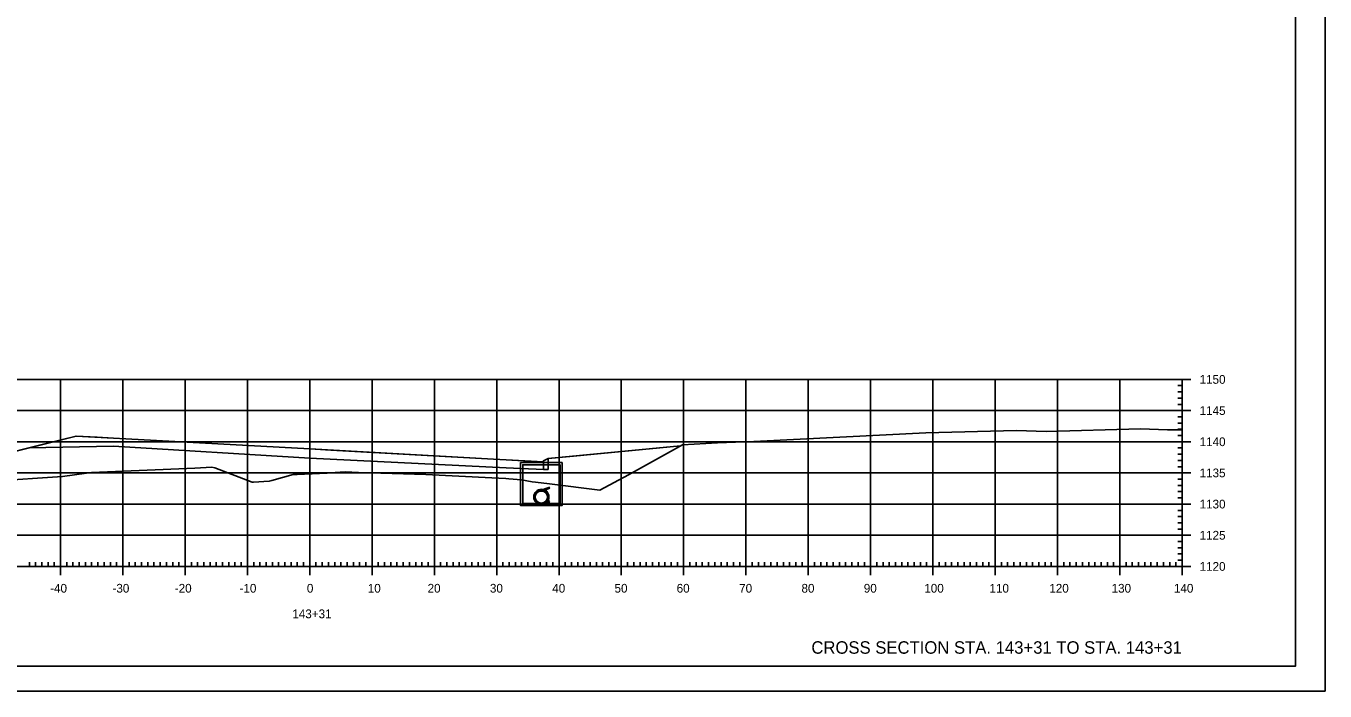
# Model space of a CAD drawing. Extents: x 1322838 to 1324533, y 339903 to 351025.
# Drawn here: x 1324118.6 to 1324327.1, y 343023.7 to 343130.4 of the extents above; entities that cross this region are included whole.
import ezdxf

# ---------------------------------------------------------------- set-up
doc = ezdxf.new("R2010")
doc.units = 0
for name, color, linetype in [('R_Alt Surface', 7, 'Continuous'), ('R_Axis', 7, 'Continuous'), ('R_Axis Annot', 7, 'Continuous'), ('R_Border', 7, 'Continuous'), ('R_Draft', 7, 'Continuous'), ('R_Exist Surface', 7, 'Continuous'), ('R_Fin Surface', 7, 'Continuous'), ('R_Grid', 7, 'Continuous'), ('R_No Plot', 7, 'Continuous')]:
    doc.layers.add(name, color=color, linetype=linetype)

msp = doc.modelspace()

# ---------------------------------------------------------------- linework, layer by layer
for points in [[(1324126.64, 343064.61), (1324104.64, 343059.11), (1324089.24, 343053.98)], [(1324201.64, 343060.49), (1324201.65, 343060.65), (1324202.4, 343060.99), (1324223.62, 343063.03), (1324223.62, 343063.03)]]:
    msp.add_lwpolyline(points)
at = {"layer": 'R_Alt Surface'}
for points in [[(1324119.06, 343062.72), (1324132.64, 343062.99), (1324164.14, 343061.05), (1324195.64, 343059.52), (1324201.64, 343059.23)], [(1324201.64, 343060.49), (1324201.64, 343059.23)], [(1324201.64, 343059.23), (1324202.4, 343059.23)], [(1324202.4, 343059.23), (1324202.4, 343060.99)]]:
    msp.add_lwpolyline(points, dxfattribs=at)
at = {"layer": 'R_Axis'}
for p, q in [((1324305.54, 343073.7), (1324302.74, 343073.7)), ((1324304.14, 343043.7), (1324304.14, 343073.7)), ((1324304.14, 343072.7), (1324303.44, 343072.7)), ((1324304.14, 343071.7), (1324303.44, 343071.7)), ((1324304.14, 343070.7), (1324303.44, 343070.7)), ((1324304.14, 343069.7), (1324303.44, 343069.7)), ((1324305.54, 343068.7), (1324302.74, 343068.7)), ((1324304.14, 343067.7), (1324303.44, 343067.7)), ((1324304.14, 343066.7), (1324303.44, 343066.7)), ((1324304.14, 343065.7), (1324303.44, 343065.7)), ((1324305.54, 343063.7), (1324302.74, 343063.7)), ((1324304.14, 343064.7), (1324303.44, 343064.7)), ((1324304.14, 343062.7), (1324303.44, 343062.7)), ((1324304.14, 343061.7), (1324303.44, 343061.7)), ((1324304.14, 343060.7), (1324303.44, 343060.7)), ((1324304.14, 343059.7), (1324303.44, 343059.7)), ((1324305.54, 343058.7), (1324302.74, 343058.7)), ((1324304.14, 343057.7), (1324303.44, 343057.7)), ((1324304.14, 343056.7), (1324303.44, 343056.7)), ((1324304.14, 343055.7), (1324303.44, 343055.7)), ((1324305.54, 343053.7), (1324302.74, 343053.7)), ((1324304.14, 343054.7), (1324303.44, 343054.7)), ((1324304.14, 343052.7), (1324303.44, 343052.7)), ((1324304.14, 343051.7), (1324303.44, 343051.7)), ((1324305.54, 343048.7), (1324302.74, 343048.7)), ((1324304.14, 343050.7), (1324303.44, 343050.7)), ((1324304.14, 343049.7), (1324303.44, 343049.7)), ((1324304.14, 343047.7), (1324303.44, 343047.7)), ((1324304.14, 343046.7), (1324303.44, 343046.7)), ((1324124.14, 343042.3), (1324124.14, 343045.1)), ((1324134.14, 343042.3), (1324134.14, 343045.1)), ((1324144.14, 343042.3), (1324144.14, 343045.1)), ((1324154.14, 343042.3), (1324154.14, 343045.1)), ((1324164.14, 343042.3), (1324164.14, 343045.1)), ((1324174.14, 343042.3), (1324174.14, 343045.1)), ((1324184.14, 343042.3), (1324184.14, 343045.1)), ((1324194.14, 343042.3), (1324194.14, 343045.1)), ((1324204.14, 343042.3), (1324204.14, 343045.1)), ((1324214.14, 343042.3), (1324214.14, 343045.1)), ((1324224.14, 343042.3), (1324224.14, 343045.1)), ((1324234.14, 343042.3), (1324234.14, 343045.1)), ((1324244.14, 343042.3), (1324244.14, 343045.1)), ((1324254.14, 343042.3), (1324254.14, 343045.1)), ((1324264.14, 343042.3), (1324264.14, 343045.1)), ((1324274.14, 343042.3), (1324274.14, 343045.1)), ((1324284.14, 343042.3), (1324284.14, 343045.1)), ((1324294.14, 343042.3), (1324294.14, 343045.1)), ((1324304.14, 343045.7), (1324303.44, 343045.7)), ((1324304.14, 343044.7), (1324303.44, 343044.7)), ((1324304.14, 343042.3), (1324304.14, 343045.1)), ((1324024.14, 343043.7), (1324304.14, 343043.7)), ((1324119.14, 343043.7), (1324119.14, 343044.4)), ((1324120.14, 343043.7), (1324120.14, 343044.4)), ((1324121.14, 343043.7), (1324121.14, 343044.4)), ((1324122.14, 343043.7), (1324122.14, 343044.4)), ((1324123.14, 343043.7), (1324123.14, 343044.4)), ((1324125.14, 343043.7), (1324125.14, 343044.4)), ((1324126.14, 343043.7), (1324126.14, 343044.4)), ((1324127.14, 343043.7), (1324127.14, 343044.4)), ((1324128.14, 343043.7), (1324128.14, 343044.4)), ((1324129.14, 343043.7), (1324129.14, 343044.4)), ((1324130.14, 343043.7), (1324130.14, 343044.4)), ((1324131.14, 343043.7), (1324131.14, 343044.4)), ((1324132.14, 343043.7), (1324132.14, 343044.4)), ((1324133.14, 343043.7), (1324133.14, 343044.4)), ((1324135.14, 343043.7), (1324135.14, 343044.4)), ((1324136.14, 343043.7), (1324136.14, 343044.4)), ((1324137.14, 343043.7), (1324137.14, 343044.4)), ((1324138.14, 343043.7), (1324138.14, 343044.4)), ((1324139.14, 343043.7), (1324139.14, 343044.4)), ((1324140.14, 343043.7), (1324140.14, 343044.4)), ((1324141.14, 343043.7), (1324141.14, 343044.4)), ((1324142.14, 343043.7), (1324142.14, 343044.4)), ((1324143.14, 343043.7), (1324143.14, 343044.4)), ((1324145.14, 343043.7), (1324145.14, 343044.4)), ((1324146.14, 343043.7), (1324146.14, 343044.4)), ((1324147.14, 343043.7), (1324147.14, 343044.4)), ((1324148.14, 343043.7), (1324148.14, 343044.4)), ((1324149.14, 343043.7), (1324149.14, 343044.4)), ((1324150.14, 343043.7), (1324150.14, 343044.4)), ((1324151.14, 343043.7), (1324151.14, 343044.4)), ((1324152.14, 343043.7), (1324152.14, 343044.4)), ((1324153.14, 343043.7), (1324153.14, 343044.4)), ((1324155.14, 343043.7), (1324155.14, 343044.4)), ((1324156.14, 343043.7), (1324156.14, 343044.4)), ((1324157.14, 343043.7), (1324157.14, 343044.4)), ((1324158.14, 343043.7), (1324158.14, 343044.4)), ((1324159.14, 343043.7), (1324159.14, 343044.4)), ((1324160.14, 343043.7), (1324160.14, 343044.4)), ((1324161.14, 343043.7), (1324161.14, 343044.4)), ((1324162.14, 343043.7), (1324162.14, 343044.4)), ((1324163.14, 343043.7), (1324163.14, 343044.4)), ((1324165.14, 343043.7), (1324165.14, 343044.4)), ((1324166.14, 343043.7), (1324166.14, 343044.4)), ((1324167.14, 343043.7), (1324167.14, 343044.4)), ((1324168.14, 343043.7), (1324168.14, 343044.4)), ((1324169.14, 343043.7), (1324169.14, 343044.4)), ((1324170.14, 343043.7), (1324170.14, 343044.4)), ((1324171.14, 343043.7), (1324171.14, 343044.4)), ((1324172.14, 343043.7), (1324172.14, 343044.4)), ((1324173.14, 343043.7), (1324173.14, 343044.4)), ((1324175.14, 343043.7), (1324175.14, 343044.4)), ((1324176.14, 343043.7), (1324176.14, 343044.4)), ((1324177.14, 343043.7), (1324177.14, 343044.4)), ((1324178.14, 343043.7), (1324178.14, 343044.4)), ((1324179.14, 343043.7), (1324179.14, 343044.4)), ((1324180.14, 343043.7), (1324180.14, 343044.4)), ((1324181.14, 343043.7), (1324181.14, 343044.4)), ((1324182.14, 343043.7), (1324182.14, 343044.4)), ((1324183.14, 343043.7), (1324183.14, 343044.4)), ((1324185.14, 343043.7), (1324185.14, 343044.4)), ((1324186.14, 343043.7), (1324186.14, 343044.4)), ((1324187.14, 343043.7), (1324187.14, 343044.4)), ((1324188.14, 343043.7), (1324188.14, 343044.4)), ((1324189.14, 343043.7), (1324189.14, 343044.4)), ((1324190.14, 343043.7), (1324190.14, 343044.4)), ((1324191.14, 343043.7), (1324191.14, 343044.4)), ((1324192.14, 343043.7), (1324192.14, 343044.4)), ((1324193.14, 343043.7), (1324193.14, 343044.4)), ((1324195.14, 343043.7), (1324195.14, 343044.4)), ((1324196.14, 343043.7), (1324196.14, 343044.4)), ((1324197.14, 343043.7), (1324197.14, 343044.4)), ((1324198.14, 343043.7), (1324198.14, 343044.4)), ((1324199.14, 343043.7), (1324199.14, 343044.4)), ((1324200.14, 343043.7), (1324200.14, 343044.4)), ((1324201.14, 343043.7), (1324201.14, 343044.4)), ((1324202.14, 343043.7), (1324202.14, 343044.4)), ((1324203.14, 343043.7), (1324203.14, 343044.4)), ((1324205.14, 343043.7), (1324205.14, 343044.4)), ((1324206.14, 343043.7), (1324206.14, 343044.4)), ((1324207.14, 343043.7), (1324207.14, 343044.4)), ((1324208.14, 343043.7), (1324208.14, 343044.4)), ((1324209.14, 343043.7), (1324209.14, 343044.4)), ((1324210.14, 343043.7), (1324210.14, 343044.4)), ((1324211.14, 343043.7), (1324211.14, 343044.4)), ((1324212.14, 343043.7), (1324212.14, 343044.4)), ((1324213.14, 343043.7), (1324213.14, 343044.4)), ((1324215.14, 343043.7), (1324215.14, 343044.4)), ((1324216.14, 343043.7), (1324216.14, 343044.4)), ((1324217.14, 343043.7), (1324217.14, 343044.4)), ((1324218.14, 343043.7), (1324218.14, 343044.4)), ((1324219.14, 343043.7), (1324219.14, 343044.4)), ((1324220.14, 343043.7), (1324220.14, 343044.4)), ((1324221.14, 343043.7), (1324221.14, 343044.4)), ((1324222.14, 343043.7), (1324222.14, 343044.4)), ((1324223.14, 343043.7), (1324223.14, 343044.4)), ((1324225.14, 343043.7), (1324225.14, 343044.4)), ((1324226.14, 343043.7), (1324226.14, 343044.4)), ((1324227.14, 343043.7), (1324227.14, 343044.4)), ((1324228.14, 343043.7), (1324228.14, 343044.4)), ((1324229.14, 343043.7), (1324229.14, 343044.4)), ((1324230.14, 343043.7), (1324230.14, 343044.4)), ((1324231.14, 343043.7), (1324231.14, 343044.4)), ((1324232.14, 343043.7), (1324232.14, 343044.4)), ((1324233.14, 343043.7), (1324233.14, 343044.4)), ((1324235.14, 343043.7), (1324235.14, 343044.4)), ((1324236.14, 343043.7), (1324236.14, 343044.4)), ((1324237.14, 343043.7), (1324237.14, 343044.4)), ((1324238.14, 343043.7), (1324238.14, 343044.4)), ((1324239.14, 343043.7), (1324239.14, 343044.4)), ((1324240.14, 343043.7), (1324240.14, 343044.4)), ((1324241.14, 343043.7), (1324241.14, 343044.4)), ((1324242.14, 343043.7), (1324242.14, 343044.4)), ((1324243.14, 343043.7), (1324243.14, 343044.4)), ((1324245.14, 343043.7), (1324245.14, 343044.4)), ((1324246.14, 343043.7), (1324246.14, 343044.4)), ((1324247.14, 343043.7), (1324247.14, 343044.4)), ((1324248.14, 343043.7), (1324248.14, 343044.4)), ((1324249.14, 343043.7), (1324249.14, 343044.4)), ((1324250.14, 343043.7), (1324250.14, 343044.4)), ((1324251.14, 343043.7), (1324251.14, 343044.4)), ((1324252.14, 343043.7), (1324252.14, 343044.4)), ((1324253.14, 343043.7), (1324253.14, 343044.4)), ((1324255.14, 343043.7), (1324255.14, 343044.4)), ((1324256.14, 343043.7), (1324256.14, 343044.4)), ((1324257.14, 343043.7), (1324257.14, 343044.4)), ((1324258.14, 343043.7), (1324258.14, 343044.4)), ((1324259.14, 343043.7), (1324259.14, 343044.4)), ((1324260.14, 343043.7), (1324260.14, 343044.4)), ((1324261.14, 343043.7), (1324261.14, 343044.4)), ((1324262.14, 343043.7), (1324262.14, 343044.4)), ((1324263.14, 343043.7), (1324263.14, 343044.4)), ((1324265.14, 343043.7), (1324265.14, 343044.4)), ((1324266.14, 343043.7), (1324266.14, 343044.4)), ((1324267.14, 343043.7), (1324267.14, 343044.4)), ((1324268.14, 343043.7), (1324268.14, 343044.4)), ((1324269.14, 343043.7), (1324269.14, 343044.4)), ((1324270.14, 343043.7), (1324270.14, 343044.4)), ((1324271.14, 343043.7), (1324271.14, 343044.4)), ((1324272.14, 343043.7), (1324272.14, 343044.4)), ((1324273.14, 343043.7), (1324273.14, 343044.4)), ((1324275.14, 343043.7), (1324275.14, 343044.4)), ((1324276.14, 343043.7), (1324276.14, 343044.4)), ((1324277.14, 343043.7), (1324277.14, 343044.4)), ((1324278.14, 343043.7), (1324278.14, 343044.4)), ((1324279.14, 343043.7), (1324279.14, 343044.4)), ((1324280.14, 343043.7), (1324280.14, 343044.4)), ((1324281.14, 343043.7), (1324281.14, 343044.4)), ((1324282.14, 343043.7), (1324282.14, 343044.4)), ((1324283.14, 343043.7), (1324283.14, 343044.4)), ((1324285.14, 343043.7), (1324285.14, 343044.4)), ((1324286.14, 343043.7), (1324286.14, 343044.4)), ((1324287.14, 343043.7), (1324287.14, 343044.4)), ((1324288.14, 343043.7), (1324288.14, 343044.4)), ((1324289.14, 343043.7), (1324289.14, 343044.4)), ((1324290.14, 343043.7), (1324290.14, 343044.4)), ((1324291.14, 343043.7), (1324291.14, 343044.4)), ((1324292.14, 343043.7), (1324292.14, 343044.4)), ((1324293.14, 343043.7), (1324293.14, 343044.4)), ((1324295.14, 343043.7), (1324295.14, 343044.4)), ((1324296.14, 343043.7), (1324296.14, 343044.4)), ((1324297.14, 343043.7), (1324297.14, 343044.4)), ((1324298.14, 343043.7), (1324298.14, 343044.4)), ((1324299.14, 343043.7), (1324299.14, 343044.4)), ((1324300.14, 343043.7), (1324300.14, 343044.4)), ((1324301.14, 343043.7), (1324301.14, 343044.4)), ((1324302.14, 343043.7), (1324302.14, 343044.4)), ((1324305.54, 343043.7), (1324302.74, 343043.7)), ((1324303.14, 343043.7), (1324303.14, 343044.4))]:
    msp.add_line(p, q, dxfattribs=at)
at = {"layer": 'R_Border'}
for q in [(1324322.32, 343233.16), (1324006.14, 343027.7)]:
    msp.add_line((1324322.32, 343027.7), q, dxfattribs=at)
at = {"layer": 'R_Exist Surface'}
for p, q in [((1324202.69, 343056.44), (1324201.71, 343056.08)), ((1324202.69, 343056.23), (1324201.71, 343055.87)), ((1324202.69, 343054.23), (1324201.71, 343053.87)), ((1324202.69, 343054.02), (1324201.71, 343053.66))]:
    msp.add_line(p, q, dxfattribs=at)
msp.add_lwpolyline([(1324090.84, 343055.89), (1324124.47, 343058.13), (1324128.31, 343058.65), (1324129.09, 343058.75), (1324145.7, 343059.49), (1324148.4, 343059.65), (1324148.92, 343059.53), (1324154.88, 343057.23), (1324155.12, 343057.24), (1324157.64, 343057.36), (1324158.03, 343057.46), (1324161.5, 343058.44), (1324162.14, 343058.47), (1324166.93, 343058.67), (1324167.37, 343058.7), (1324169.87, 343058.86), (1324171.96, 343058.79), (1324182.79, 343058.45), (1324193.36, 343057.91), (1324195.59, 343057.81), (1324196.1, 343057.76), (1324198.11, 343057.61), (1324199.83, 343057.29), (1324200.37, 343057.24), (1324202.64, 343056.93), (1324210.7, 343055.93), (1324215.27, 343058.41), (1324223.96, 343063.22), (1324229.57, 343063.51), (1324235.43, 343063.74), (1324263.03, 343065.15), (1324277.57, 343065.5), (1324282.3, 343065.36), (1324297.45, 343065.75), (1324301.78, 343065.61), (1324304.14, 343065.61)], dxfattribs=at)
for points in [[(1324201.31, 343060.35), (1324204.64, 343060.35), (1324204.64, 343053.46), (1324201.31, 343053.46), (1324197.97, 343053.46), (1324197.97, 343060.35)], [(1324201.31, 343060.02), (1324204.31, 343060.02), (1324204.31, 343053.79), (1324201.31, 343053.79), (1324198.31, 343053.79), (1324198.31, 343060.02)]]:
    msp.add_lwpolyline(points, close=True, dxfattribs=at)
for centre, radius in [((1324201.31, 343054.87), 1.21), ((1324201.31, 343054.79), 1.21), ((1324201.31, 343054.87), 1), ((1324201.31, 343054.79), 1)]:
    msp.add_circle(centre, radius, dxfattribs=at)
at = {"layer": 'R_Fin Surface'}
for points in [[(1324112.47, 343061.07), (1324119.06, 343062.72), (1324121.83, 343063.41), (1324126.64, 343064.61), (1324130, 343064.43), (1324132.64, 343064.28), (1324134.64, 343064.17), (1324164.14, 343062.55), (1324167.51, 343062.36), (1324193.64, 343060.93), (1324195.64, 343060.82), (1324195.64, 343060.82), (1324198.45, 343060.66), (1324201.64, 343060.49), (1324201.65, 343060.65), (1324202.4, 343060.99), (1324206.48, 343061.38), (1324223.62, 343063.03)], [(1324126.64, 343064.61), (1324132.64, 343064.28), (1324134.64, 343064.17), (1324164.14, 343062.55), (1324193.64, 343060.93), (1324195.64, 343060.82), (1324201.64, 343060.49)]]:
    msp.add_lwpolyline(points, dxfattribs=at)
at = {"layer": 'R_Grid'}
for p, q in [((1324024.14, 343073.7), (1324304.14, 343073.7)), ((1324124.14, 343043.7), (1324124.14, 343073.7)), ((1324134.14, 343043.7), (1324134.14, 343073.7)), ((1324144.14, 343043.7), (1324144.14, 343073.7)), ((1324154.14, 343043.7), (1324154.14, 343073.7)), ((1324164.14, 343043.7), (1324164.14, 343073.7)), ((1324174.14, 343043.7), (1324174.14, 343073.7)), ((1324184.14, 343043.7), (1324184.14, 343073.7)), ((1324194.14, 343043.7), (1324194.14, 343073.7)), ((1324204.14, 343043.7), (1324204.14, 343073.7)), ((1324214.14, 343043.7), (1324214.14, 343073.7)), ((1324224.14, 343043.7), (1324224.14, 343073.7)), ((1324234.14, 343043.7), (1324234.14, 343073.7)), ((1324244.14, 343043.7), (1324244.14, 343073.7)), ((1324254.14, 343043.7), (1324254.14, 343073.7)), ((1324264.14, 343043.7), (1324264.14, 343073.7)), ((1324274.14, 343043.7), (1324274.14, 343073.7)), ((1324284.14, 343043.7), (1324284.14, 343073.7)), ((1324294.14, 343043.7), (1324294.14, 343073.7)), ((1324304.14, 343043.7), (1324304.14, 343073.7)), ((1324024.14, 343068.7), (1324304.14, 343068.7)), ((1324024.14, 343063.7), (1324304.14, 343063.7)), ((1324024.14, 343058.7), (1324304.14, 343058.7)), ((1324024.14, 343053.7), (1324304.14, 343053.7)), ((1324024.14, 343048.7), (1324304.14, 343048.7)), ((1324024.14, 343043.7), (1324304.14, 343043.7))]:
    msp.add_line(p, q, dxfattribs=at)
at = {"layer": 'R_No Plot'}
msp.add_line((1323993.74, 343023.72), (1324327.07, 343023.72), dxfattribs=at)
for points in [[(1323993.73, 343237.06), (1324327.07, 343237.06), (1324327.07, 343023.72), (1323993.73, 343023.72)], [(1324240.06, 343233.16), (1324259.68, 343233.16), (1324259.68, 343223.28), (1324275.79, 343223.28), (1324298.99, 343223.28), (1324299.11, 343195.13), (1324322.32, 343195.13), (1324322.32, 343027.7), (1324006.14, 343027.7), (1324006.14, 343233.16)]]:
    msp.add_lwpolyline(points, close=True, dxfattribs=at)

# ---------------------------------------------------------------- texts
at = {"layer": 'R_Axis Annot'}
for s, p in [('1150', (1324306.94, 343073)), ('1145', (1324306.94, 343068)), ('1140', (1324306.94, 343063)), ('1135', (1324306.94, 343058)), ('1130', (1324306.94, 343053)), ('1125', (1324306.94, 343048)), ('1120', (1324306.94, 343043)), ('-40', (1324122.48, 343039.5)), ('-30', (1324132.48, 343039.5)), ('-20', (1324142.48, 343039.5)), ('-10', (1324152.87, 343039.5)), ('0', (1324163.68, 343039.5)), ('10', (1324173.45, 343039.5)), ('20', (1324183.05, 343039.5)), ('30', (1324193.05, 343039.5)), ('40', (1324203.05, 343039.5)), ('50', (1324213.05, 343039.5)), ('60', (1324223.02, 343039.5)), ('70', (1324233.05, 343039.5)), ('80', (1324243.05, 343039.5)), ('90', (1324253.05, 343039.5)), ('100', (1324262.76, 343039.5)), ('110', (1324273.22, 343039.5)), ('120', (1324282.82, 343039.5)), ('130', (1324292.82, 343039.5)), ('140', (1324302.82, 343039.5)), ('143+31', (1324161.34, 343035.4))]:
    msp.add_text(s, height=1.4, dxfattribs=at).set_placement(p)
at = {"layer": 'R_Draft'}
msp.add_text('CROSS SECTION STA. 143+31 TO STA. 143+31', height=2, dxfattribs=at).set_placement((1324244.64, 343029.7))

doc.saveas('drawing.dxf')
